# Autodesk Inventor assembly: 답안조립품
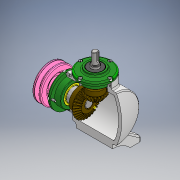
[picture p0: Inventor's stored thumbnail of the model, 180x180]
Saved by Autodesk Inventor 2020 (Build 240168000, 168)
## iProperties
Created: 2023-12
Part Number: 답안조립품
Document SubType Name: Weldment
Designer: 1강의실14
Weld Material: Welded Aluminum-6061
Author: 1강의실14
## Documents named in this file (17)
- C:\Users\1강의실14\Desktop\731203V1008\답안조립품.iam
- C:\Users\1강의실14\Desktop\731203V1008\본체.ipt
- C:\Users\1강의실14\Desktop\731203V1008\커버.ipt
- C:\Users\1강의실14\Desktop\731203V1008\베어링 6203.ipt
- C:\Users\1강의실14\Desktop\731203V1008\오일실 17 x 32 x 8.ipt
- C:\Users\1강의실14\Desktop\731203V1008\메인 축.ipt
- 메인 축.ipt
- C:\Users\1강의실14\Desktop\731203V1008\키 4 x 4 x 14.ipt
- C:\Users\1강의실14\Desktop\731203V1008\V-벨트풀리.ipt
- C:\Users\1강의실14\Desktop\731203V1008\육각볼트 M4 x 8.ipt
- C:\Users\1강의실14\Desktop\731203V1008\와셔 4 x 16.ipt
- C:\Users\1강의실14\Desktop\731203V1008\메인 베벨기어.ipt
- C:\Users\1강의실14\Desktop\731203V1008\키 5 x 5 x 14.ipt
- C:\Users\1강의실14\Desktop\731203V1008\서브 축.ipt
- 서브 축.ipt
- C:\Users\1강의실14\Desktop\731203V1008\서브 베벨기어.ipt
- C:\Users\1강의실14\Desktop\731203V1008\볼트 M4 x 10.ipt
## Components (1 placed, 1 different names)
1. V-벨트풀리:1
